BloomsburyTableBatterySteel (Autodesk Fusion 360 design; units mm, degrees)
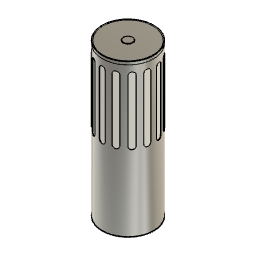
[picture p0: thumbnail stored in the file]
sketch "Sketch2" plane through (0, 0, 0) normal (0, 0, 1) x axis (1, 0, 0)
  circle C1 centre (0, 0) radius 27
  point P1 (0, 0)
  point P2 (0, 0)
  coincident P1 P2
  dimension "d1" diameter C1 = 54
extrude "Extrude1" new body sketch "Sketch2" along normal blind 158
shell "Shell1" innerThickness 1
sketch "Sketch3" plane through (0, 0, 158) normal (0, 0, 1) x axis (-1, 0, 0)
  circle C1 centre (0, 0) radius 26
  circle C2 centre (0, 0) radius 27
  circle C3 centre (0, 0) radius 27
  point P1 (0, 0)
  point P3 (0, 0)
  coincident P1 P3
  dimension "d69" diameter C3 = 54
extrude "Extrude2" new body sketch "Sketch3" along normal blind 0.5
sketch "Sketch4" plane through (0, 0, 0) normal (0, 0, -1) x axis (1, 0, 0)
  circle C1 centre (0, 0) radius 26
  circle C2 centre (0, 0) radius 27
  circle C3 centre (0, 0) radius 27
  point P1 (0, 0)
  point P3 (0, 0)
  coincident P1 P3
  dimension "d70" diameter C3 = 54
extrude "Extrude3" new body sketch "Sketch4" along normal blind 0.5
work_plane "WorkPlane1" AlongDistance -50
sketch "Sketch5" plane through (0, -50, 0) normal (0, 1, 0) x axis (1, 0, 0)
  line L1 (27, -158.5) -> (-27, -158.5)
  line L2 (0, -2.5) -> (0, -20)
  line L3 (-3, -81.5) -> (-3, -145.5)
  line L4 (0, -125) -> (0, -85)
  line L5 (3, -81.5) -> (3, -145.5)
  arc A1 centre (0, -145.5) radius 3 clockwise from (0, -148.5) to (-3, -145.5)
  arc A2 centre (0, -81.5) radius 3 clockwise from (-3, -81.5) to (0, -78.5)
  arc A3 centre (0, -145.5) radius 3 clockwise from (3, -145.5) to (0, -148.5)
  arc A4 centre (0, -81.5) radius 3 clockwise from (0, -78.5) to (3, -81.5)
  point P9 (0, -145.5)
  point P8 (0, -148.5)
  point P13 (0, -81.5)
  point P12 (0, -78.5)
  point P6 (-3, -145.5)
  point P15 (3, -145.5)
  point P7 (-3, -81.5)
  point P17 (3, -81.5)
  point P16 (0, -148.5)
  point P19 (0, -78.5)
  vertical L3
  tangent L3 A1
  vertical L4
  coincident P9 L4
  coincident P8 L4
  tangent L3 A2
  coincident L4 P13
  coincident L4 P12
  symmetric P6 L4 P15
  symmetric P7 L4 P17
  symmetric P8 L4 P16
  symmetric A1 L4 A3
  symmetric L4 P12 P19
  symmetric L4 A2 A4
  dimension "d75" distance L3 L4 = 3
  dimension "d77" distance P8 P19 = 70
  dimension "d78" distance L1 P8 = 10
emboss "Emboss1" sketch "Sketch5" Depth -8 Horizontal Distance 0 Vertical Distance 0 Rotation Angle 0
fillet "Fillet7" radius 0.1
circular_pattern "C-Pattern1" countU 14 TotalAngle 360
fillet "Fillet2" radius 0.1
sketch "Sketch6" plane through (0, 0, 0) normal (0, 0, 1) x axis (-1, 0, 0)
  circle C1 centre (0, 0) radius 26.9
  circle C2 centre (0, 0) radius 26.75
  point P1 (0, 0)
  point P3 (0, 0)
  coincident P1 P3
  dimension "d25" diameter C2 = 53.5
extrude "Extrude4" new body sketch "Sketch6" profile of C2 along normal blind 155
work_plane "WorkPlane2" RotateAngle 0
sketch "Sketch7" plane through (0, 27, 16.5829) normal (0, 1, 0) x axis (1, 0, 0)
  line L1 (-27, 16.9829) -> (27, 16.9829)
  circle C1 centre (0, 9.4829) radius 5.5
  circle C2 centre (0, 9.4829) radius 3.5
  point P1 (0, 0)
  point P2 (0, 9.4829)
  vertical P1 P2
  concentric C1 C2
  dimension "d29" diameter C1 = 11
  dimension "d30" distance P2 L1 = 7.5
  dimension "d31" diameter C2 = 7
sketch "Sketch8" plane through (0, 27, 16.5829) normal (0, 1, 0) x axis (1, 0, 0)
  circle C1 centre (0, 16) radius 3
  dimension "d38" diameter C1 = 6
sketch "Sketch9" plane through (0, 0, -0.5) normal (0, 0, -1) x axis (1, 0, 0)
  circle C1 centre (0, 0) radius 26.9
  circle C2 centre (0, 0) radius 6
  point P1 (0, 0)
  point P3 (0, 0)
  coincident P1 P3
  dimension "d43" diameter C2 = 12
extrude "Extrude8" cut sketch "Sketch9" profile of C2 against normal blind 0.5 taper -40
sketch "Sketch10" plane through (0, 0, 0) normal (0, 0, -1) x axis (1, 0, 0)
  circle C1 centre (0, 0) radius 26.75
  circle C2 centre (0, 0) radius 5.58
  point P1 (0, 0)
  point P3 (0, 0)
  coincident P1 P3
extrude "Extrude9" new body sketch "Sketch10" profile of C2 to an object
sketch "Sketch11" plane through (0, 0, -0.5) normal (0, 0, -1) x axis (1, 0, 0)
  line L1 (-2.3094, 0) -> (-1.1547, 2)
  line L2 (-1.1547, -2) -> (-2.3094, 0)
  line L3 (1.1547, -2) -> (-1.1547, -2)
  line L4 (2.3094, 0) -> (1.1547, -2)
  line L5 (1.1547, 2) -> (2.3094, 0)
  line L6 (-1.1547, 2) -> (1.1547, 2)
  circle C1 centre (0, 0) radius 5.58
  point P1 (0, 0)
  point P9 (0, 0)
  coincident P1 P9
  dimension "d51" distance P9 L6 = 2
extrude "Extrude10" cut sketch "Sketch11" profile of L1 L2 L3 L4 L5 L6 against normal blind 0.49
fillet "Fillet4" radius 0.1
sketch "Sketch12" plane through (0, 0, 158.5) normal (0, 0, 1) x axis (-1, 0, 0)
  circle C1 centre (0, 0) radius 26.9
  circle C2 centre (0, 0) radius 5
  point P1 (0, 0)
  point P3 (0, 0)
  coincident P1 P3
  dimension "d56" diameter C2 = 10
extrude "Extrude14" cut sketch "Sketch12" profile of C2 against normal blind 0.5
sketch "Sketch14" plane through (0, 0, 155) normal (0, 0, 1) x axis (-1, 0, 0)
  circle C1 centre (0, 0) radius 26.75
  circle C2 centre (0, 0) radius 4.75
  point P1 (0, 0)
  point P3 (0, 0)
  coincident P1 P3
  dimension "d83" diameter C2 = 9.5
extrude "Extrude15" new body sketch "Sketch14" profile of C2 along normal blind 3.7
fillet "Fillet8" radius 0.2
